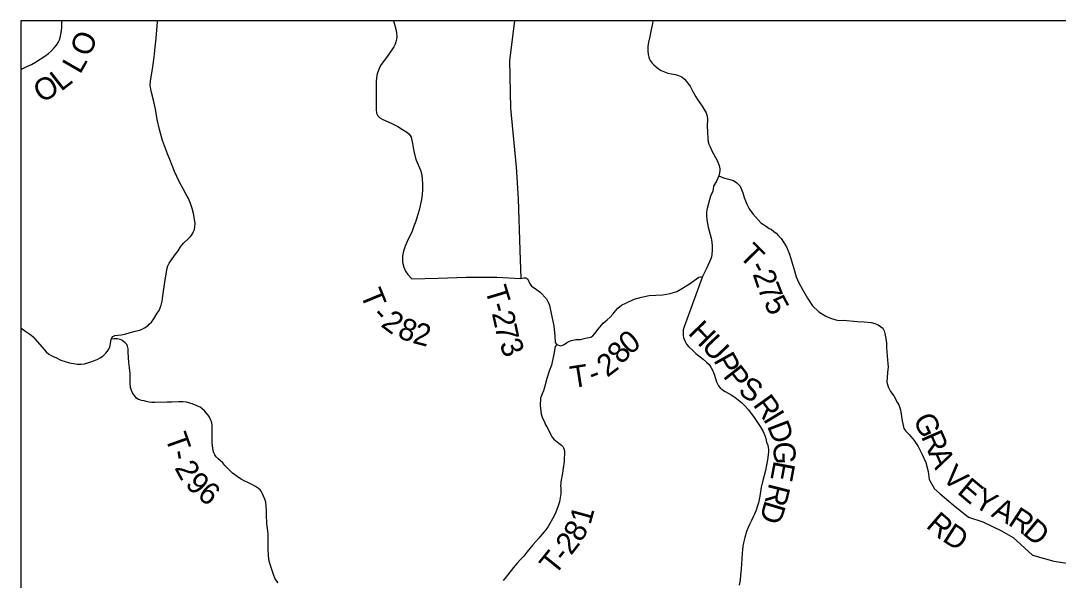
# Model space of a CAD drawing. Extents: x -10.5 to 40.6, y -3.2 to 22.
# Drawn here: x -10.544 to -7.857, y 19.45 to 20.9 of the extents above; entities that cross this region are included whole.
import ezdxf

# ---------------------------------------------------------------- set-up
doc = ezdxf.new("R2010")
doc.units = 0
for name, color, linetype in [('GM_X_County_Road', 7, 'Continuous'), ('GM_X_Township_Road', 7, 'Continuous'), ('GM_X_Township_Road_Text', 7, 'Continuous'), ('GM_X_Township_Text', 7, 'Continuous')]:
    doc.layers.add(name, color=color, linetype=linetype)

msp = doc.modelspace()

# ---------------------------------------------------------------- linework, layer by layer
at = {"layer": 'GM_X_County_Road'}
msp.add_lwpolyline([(-10.5445, 20.104), (-10.5309, 20.0945), (-10.5184, 20.0862), (-10.5127, 20.0809), (-10.5076, 20.0753), (-10.4893, 20.0539), (-10.4786, 20.0422), (-10.4714, 20.036), (-10.4653, 20.0321), (-10.4608, 20.0299), (-10.454, 20.0268), (-10.4403, 20.0206), (-10.4292, 20.0168), (-10.4178, 20.0131), (-10.4077, 20.0112), (-10.398, 20.0103), (-10.3881, 20.0102), (-10.3795, 20.011), (-10.3707, 20.0132), (-10.3606, 20.0168), (-10.3534, 20.019), (-10.3446, 20.0225), (-10.3388, 20.0259), (-10.3321, 20.031), (-10.3243, 20.0385), (-10.3172, 20.0474), (-10.3139, 20.0551), (-10.312, 20.0632), (-10.3099, 20.0751), (-10.3082, 20.0781), (-10.3056, 20.0813), (-10.3009, 20.0839), (-10.2931, 20.0848), (-10.2845, 20.086), (-10.2746, 20.088), (-10.2609, 20.0916), (-10.2482, 20.0952), (-10.2366, 20.0984), (-10.2296, 20.1009), (-10.2235, 20.104), (-10.2157, 20.1094), (-10.2114, 20.1136), (-10.2058, 20.1191), (-10.1995, 20.1278), (-10.1907, 20.1417), (-10.1863, 20.1492), (-10.1835, 20.1556), (-10.1808, 20.1631), (-10.1783, 20.1728), (-10.1761, 20.1867), (-10.171, 20.2227), (-10.1669, 20.2494), (-10.165, 20.2589), (-10.1632, 20.2651), (-10.16, 20.2715), (-10.1542, 20.2803), (-10.1462, 20.2912), (-10.137, 20.3039), (-10.1304, 20.3138), (-10.1263, 20.3194), (-10.1231, 20.3237), (-10.1108, 20.3349), (-10.1044, 20.3409), (-10.1012, 20.345), (-10.0988, 20.3497), (-10.0968, 20.3535), (-10.0948, 20.3587), (-10.0935, 20.366), (-10.0931, 20.3743), (-10.0945, 20.3858), (-10.0973, 20.4005), (-10.1004, 20.413), (-10.1048, 20.4259), (-10.1103, 20.4393), (-10.1156, 20.4499), (-10.1236, 20.4641), (-10.1313, 20.4782), (-10.1402, 20.4967), (-10.1458, 20.5095), (-10.158, 20.54), (-10.164, 20.5554), (-10.1721, 20.5756), (-10.1771, 20.5893), (-10.1848, 20.6177), (-10.191, 20.6443), (-10.1958, 20.6705), (-10.2008, 20.6937), (-10.206, 20.7142), (-10.2078, 20.7226), (-10.2093, 20.733), (-10.2082, 20.7437), (-10.2027, 20.7803), (-10.1989, 20.8054), (-10.1961, 20.8317), (-10.1933, 20.8547), (-10.1907, 20.8868), (-10.1905, 20.8973), (-10.1903, 20.9)], dxfattribs=at)
at = {"layer": 'GM_X_Township_Road'}
for points in [[(-10.5445, 20.7732), (-10.5408, 20.7755), (-10.5289, 20.7813), (-10.5167, 20.787), (-10.5067, 20.7924), (-10.5036, 20.794), (-10.4825, 20.8079), (-10.4723, 20.815), (-10.4647, 20.822), (-10.4579, 20.8295), (-10.452, 20.8365), (-10.4474, 20.8434), (-10.4437, 20.8509), (-10.4411, 20.8604), (-10.4394, 20.8694), (-10.4382, 20.8819), (-10.4381, 20.889), (-10.4384, 20.8953), (-10.4377, 20.9)], [(-9.5792, 20.9), (-9.5772, 20.8933), (-9.5732, 20.8784), (-9.5709, 20.8689), (-9.5703, 20.8584), (-9.5709, 20.8521), (-9.5725, 20.8453), (-9.5746, 20.8396), (-9.5783, 20.8324), (-9.5929, 20.8107), (-9.6122, 20.7836), (-9.6179, 20.772), (-9.6213, 20.762), (-9.623, 20.7529), (-9.6234, 20.7414), (-9.6242, 20.7113), (-9.624, 20.671), (-9.6228, 20.6608), (-9.6193, 20.6539), (-9.6145, 20.6481), (-9.6082, 20.645), (-9.5829, 20.6337), (-9.5681, 20.626), (-9.556, 20.6185), (-9.5447, 20.6114), (-9.5392, 20.6068), (-9.5355, 20.6029), (-9.5335, 20.5986), (-9.5298, 20.5818), (-9.5272, 20.5661), (-9.5255, 20.5583), (-9.5232, 20.5474), (-9.5198, 20.539), (-9.509, 20.5124), (-9.5066, 20.5038), (-9.5055, 20.4978), (-9.5049, 20.4902), (-9.5039, 20.4764), (-9.5038, 20.4631), (-9.5047, 20.4487), (-9.5062, 20.4363), (-9.5123, 20.4088), (-9.5163, 20.3951), (-9.5213, 20.3809), (-9.526, 20.3674), (-9.5307, 20.3547), (-9.5438, 20.3278), (-9.5483, 20.3159), (-9.5532, 20.3027), (-9.556, 20.2898), (-9.5554, 20.2739), (-9.5517, 20.2617), (-9.5475, 20.2511), (-9.5417, 20.2423), (-9.5312, 20.2309), (-9.4636, 20.233), (-9.391, 20.2354), (-9.3113, 20.2354), (-9.2489, 20.2317)], [(-9.2653, 20.9), (-9.2782, 20.7971), (-9.2754, 20.6738), (-9.2614, 20.5209), (-9.2562, 20.4386), (-9.2514, 20.3057), (-9.2489, 20.2317)], [(-8.9073, 20.9), (-8.9084, 20.8932), (-8.9118, 20.8765), (-8.9151, 20.8592), (-8.9179, 20.8446), (-8.9198, 20.8334), (-8.9201, 20.8221), (-8.9191, 20.8128), (-8.9177, 20.806), (-8.9157, 20.8), (-8.914, 20.7967), (-8.9117, 20.7931), (-8.9089, 20.7896), (-8.9048, 20.7857), (-8.8989, 20.7807), (-8.892, 20.7756), (-8.8852, 20.7712), (-8.8771, 20.7673), (-8.8679, 20.7644), (-8.8585, 20.7626), (-8.8488, 20.7605), (-8.8406, 20.7579), (-8.8366, 20.7562), (-8.8313, 20.7534), (-8.8251, 20.7484), (-8.8197, 20.7427), (-8.8146, 20.7356), (-8.8108, 20.7301), (-8.8032, 20.7164), (-8.7957, 20.7029), (-8.7912, 20.6962), (-8.7794, 20.6788), (-8.7738, 20.67), (-8.7693, 20.661), (-8.7667, 20.6527), (-8.7657, 20.6443), (-8.7663, 20.6275), (-8.7653, 20.6108), (-8.7649, 20.5941), (-8.7639, 20.5863), (-8.762, 20.5798), (-8.7589, 20.5729), (-8.754, 20.5628), (-8.7404, 20.5381), (-8.7355, 20.5245), (-8.7337, 20.5162), (-8.7333, 20.512), (-8.7342, 20.5056), (-8.736, 20.498), (-8.742, 20.4838), (-8.7497, 20.4711), (-8.7505, 20.4645), (-8.7519, 20.4587), (-8.7574, 20.4449), (-8.7633, 20.4266), (-8.7669, 20.4096), (-8.7678, 20.403), (-8.7683, 20.3955), (-8.7673, 20.384), (-8.7657, 20.3743), (-8.7635, 20.3646), (-8.7559, 20.3363), (-8.7544, 20.3264), (-8.7534, 20.3165), (-8.753, 20.3054), (-8.754, 20.2942), (-8.7554, 20.2883), (-8.7567, 20.2828), (-8.768, 20.2582), (-8.7788, 20.2372), (-8.8263, 20.1065), (-8.8281, 20.0988), (-8.8288, 20.0915), (-8.8282, 20.0845), (-8.8276, 20.0793), (-8.8261, 20.0747), (-8.8237, 20.069), (-8.8197, 20.0621), (-8.8135, 20.0545), (-8.8047, 20.0458), (-8.7955, 20.0378), (-8.7767, 20.0227), (-8.768, 20.0154), (-8.7615, 20.0086), (-8.7567, 20.0018), (-8.7523, 19.9942), (-8.7484, 19.9839), (-8.745, 19.9723), (-8.7419, 19.9639), (-8.7398, 19.9586), (-8.7372, 19.9541), (-8.7324, 19.9484), (-8.7267, 19.9436), (-8.7196, 19.9389), (-8.7038, 19.9304), (-8.6946, 19.9245), (-8.6858, 19.9178), (-8.6777, 19.9105), (-8.6686, 19.9016), (-8.6597, 19.8913), (-8.6448, 19.8719), (-8.6391, 19.8635), (-8.6292, 19.8487), (-8.6211, 19.835), (-8.6171, 19.825), (-8.6148, 19.8175), (-8.6123, 19.8081), (-8.6096, 19.7997), (-8.6084, 19.7941), (-8.6078, 19.7888), (-8.6076, 19.7815), (-8.6099, 19.7616), (-8.6131, 19.7437), (-8.6154, 19.7344), (-8.6231, 19.7053), (-8.6262, 19.6908), (-8.6302, 19.6679), (-8.6337, 19.6508), (-8.6368, 19.6403), (-8.6394, 19.6315), (-8.6417, 19.6253), (-8.644, 19.6207), (-8.6471, 19.614), (-8.6518, 19.6044), (-8.657, 19.5946), (-8.6604, 19.5868), (-8.6646, 19.5763), (-8.6691, 19.5606), (-8.6726, 19.5471), (-8.674, 19.5384), (-8.6748, 19.529), (-8.6755, 19.5197), (-8.6787, 19.4785), (-8.6799, 19.4627), (-8.6812, 19.45), (-8.6832, 19.4369)], [(-8.736, 20.498), (-8.7244, 20.4931), (-8.6982, 20.4858), (-8.6897, 20.4797), (-8.6811, 20.471), (-8.6739, 20.4536), (-8.6704, 20.4421), (-8.664, 20.4243), (-8.6578, 20.4126), (-8.6484, 20.3994), (-8.6271, 20.3763), (-8.6203, 20.3715), (-8.6151, 20.3686), (-8.6093, 20.3637), (-8.6061, 20.3616), (-8.6006, 20.3595), (-8.5934, 20.3541), (-8.5875, 20.3491), (-8.5812, 20.3427), (-8.5745, 20.3352), (-8.5682, 20.3265), (-8.5608, 20.3142), (-8.5533, 20.2952), (-8.5402, 20.2517), (-8.5358, 20.2365), (-8.5289, 20.2205), (-8.5199, 20.2051), (-8.5068, 20.1812), (-8.4935, 20.1614), (-8.477, 20.1458), (-8.4586, 20.1345), (-8.4468, 20.1291), (-8.433, 20.1245), (-8.4244, 20.1231), (-8.4131, 20.1235), (-8.3781, 20.1205), (-8.3595, 20.1197), (-8.3414, 20.1178), (-8.3323, 20.1157), (-8.3232, 20.1122), (-8.3171, 20.1077), (-8.3115, 20.1032), (-8.3079, 20.0963), (-8.3064, 20.0897), (-8.3037, 20.0765), (-8.3018, 20.0645), (-8.3014, 20.0522), (-8.298, 20.0111), (-8.2972, 20.0033), (-8.2995, 19.9882), (-8.3006, 19.9635), (-8.2977, 19.9507), (-8.2916, 19.939), (-8.2825, 19.9274), (-8.2729, 19.9095), (-8.2701, 19.9043), (-8.2658, 19.8915), (-8.2613, 19.8634), (-8.2565, 19.8432), (-8.2514, 19.8358), (-8.2435, 19.8278), (-8.2304, 19.8118), (-8.2199, 19.7965), (-8.2098, 19.7757), (-8.2, 19.7547), (-8.1939, 19.7314), (-8.1913, 19.7107), (-8.1777, 19.6866), (-8.163, 19.6741), (-8.1287, 19.6457), (-8.0894, 19.6137), (-8.0525, 19.6014), (-8.0038, 19.5779), (-7.9741, 19.561), (-7.9233, 19.5147), (-7.8682, 19.4996), (-7.8285, 19.4929)], [(-9.2489, 20.2317), (-9.2417, 20.2338), (-9.2359, 20.2338), (-9.2311, 20.2306), (-9.2268, 20.2197), (-9.221, 20.2123), (-9.212, 20.2057), (-9.1992, 20.1966), (-9.1823, 20.1792), (-9.1782, 20.1708), (-9.175, 20.1627), (-9.1704, 20.1412), (-9.1638, 20.1096), (-9.1608, 20.0827), (-9.1597, 20.0663), (-9.1554, 20.0609)], [(-9.1554, 20.0609), (-9.1514, 20.0594), (-9.1453, 20.0575), (-9.142, 20.058), (-9.1365, 20.0607), (-9.1307, 20.0649), (-9.1227, 20.0695), (-9.1175, 20.071), (-9.1064, 20.0734), (-9.0943, 20.0741), (-9.0811, 20.077), (-9.0677, 20.08), (-9.0628, 20.0837), (-9.0576, 20.0895), (-9.0483, 20.1005), (-9.0359, 20.1161), (-9.0253, 20.1252), (-9.0178, 20.1315), (-9.0098, 20.14), (-9.0038, 20.1481), (-8.9981, 20.1552), (-8.9886, 20.1628), (-8.9753, 20.1691), (-8.9551, 20.1782), (-8.9365, 20.1832), (-8.9164, 20.1882), (-8.8997, 20.1883), (-8.881, 20.1897), (-8.8624, 20.1932), (-8.8448, 20.1981), (-8.8299, 20.2068), (-8.8124, 20.2184), (-8.7876, 20.2352), (-8.784, 20.2365), (-8.7788, 20.2372)], [(-10.2221, 19.9143), (-10.225, 19.9151), (-10.2313, 19.9161), (-10.2358, 19.917), (-10.2396, 19.9185), (-10.2436, 19.921), (-10.2474, 19.9248), (-10.251, 19.9293), (-10.2546, 19.9355), (-10.2578, 19.9417), (-10.2598, 19.9494), (-10.2612, 19.9603), (-10.2612, 19.9769), (-10.261, 19.9859), (-10.2629, 20.0005), (-10.2642, 20.0145), (-10.2661, 20.0408), (-10.2666, 20.0493), (-10.2682, 20.0564), (-10.27, 20.061), (-10.274, 20.0653), (-10.278, 20.0686), (-10.2827, 20.0718), (-10.2868, 20.0738), (-10.2948, 20.0757), (-10.3022, 20.0759), (-10.3099, 20.0751)], [(-9.1554, 20.0609), (-9.16, 20.0557), (-9.1634, 20.0354), (-9.17, 20.007), (-9.1757, 19.9913), (-9.1817, 19.9727), (-9.1866, 19.9525), (-9.1884, 19.9467), (-9.1903, 19.9408), (-9.1939, 19.9326), (-9.1984, 19.922), (-9.199, 19.903), (-9.1974, 19.8878), (-9.1965, 19.8799), (-9.1949, 19.8751), (-9.1935, 19.8723), (-9.1865, 19.8581), (-9.1852, 19.853), (-9.1814, 19.848), (-9.1711, 19.8268), (-9.1684, 19.8215), (-9.1634, 19.8151), (-9.151, 19.8054), (-9.1434, 19.7997), (-9.1403, 19.7965), (-9.1386, 19.7934), (-9.1369, 19.7887), (-9.1359, 19.7825), (-9.1356, 19.7767), (-9.1364, 19.7662), (-9.1372, 19.7572), (-9.1391, 19.7402), (-9.1411, 19.7277), (-9.1452, 19.7052), (-9.1458, 19.7005), (-9.1459, 19.6957), (-9.1452, 19.6879), (-9.1452, 19.6781), (-9.1455, 19.674), (-9.1461, 19.6689), (-9.1491, 19.6531), (-9.1529, 19.64), (-9.1586, 19.6259), (-9.1638, 19.6154), (-9.1784, 19.5893), (-9.1846, 19.5802), (-9.19, 19.5739), (-9.2028, 19.5586), (-9.2176, 19.5418), (-9.2331, 19.5222), (-9.2416, 19.5124), (-9.2497, 19.504), (-9.2585, 19.4937), (-9.2642, 19.4872), (-9.2874, 19.4587), (-9.2947, 19.4494)], [(-9.8774, 19.4428), (-9.8834, 19.4505), (-9.8864, 19.4556), (-9.8892, 19.4623), (-9.8968, 19.4856), (-9.9007, 19.4991), (-9.9026, 19.5141), (-9.9039, 19.5309), (-9.9037, 19.553), (-9.9037, 19.5696), (-9.9045, 19.5778), (-9.9073, 19.596), (-9.9075, 19.6206), (-9.908, 19.6318), (-9.9085, 19.6411), (-9.9099, 19.6524), (-9.9122, 19.66), (-9.9154, 19.6679), (-9.9187, 19.6754), (-9.9213, 19.6805), (-9.9243, 19.6841), (-9.9288, 19.6879), (-9.9363, 19.6925), (-9.9438, 19.6971), (-9.9565, 19.7032), (-9.9657, 19.7077), (-9.9733, 19.7121), (-9.98, 19.7162), (-9.9877, 19.7216), (-9.9956, 19.7276), (-10.0043, 19.7359), (-10.0158, 19.7469), (-10.0214, 19.7541), (-10.0282, 19.7599), (-10.0332, 19.7647), (-10.0379, 19.7698), (-10.0415, 19.7751), (-10.0442, 19.7801), (-10.0464, 19.7864), (-10.0478, 19.7986), (-10.0484, 19.8062), (-10.0485, 19.8208), (-10.0489, 19.8527), (-10.0504, 19.8614), (-10.0535, 19.8683), (-10.0568, 19.8743), (-10.0602, 19.8787), (-10.0635, 19.8829), (-10.0684, 19.8889), (-10.075, 19.8948), (-10.0799, 19.8983), (-10.0843, 19.9005), (-10.0901, 19.903), (-10.1001, 19.907), (-10.1068, 19.9092), (-10.1115, 19.9105), (-10.1158, 19.9111), (-10.1243, 19.9119), (-10.1348, 19.9119), (-10.1532, 19.9116), (-10.1655, 19.9115), (-10.1969, 19.9103), (-10.2048, 19.9105), (-10.2119, 19.9112), (-10.2159, 19.9122), (-10.2192, 19.9135), (-10.2221, 19.9143)]]:
    msp.add_lwpolyline(points, dxfattribs=at)
at = {"layer": 'GM_X_Township_Text'}
msp.add_lwpolyline([(-6.192, 17.3965), (-6.1792, 18.1778), (-6.179, 18.1863), (-6.1678, 18.8746), (-6.1678, 18.8755), (-6.1618, 20.9), (-10.5445, 20.9), (-10.5445, 19.4241)], dxfattribs=at)

# ---------------------------------------------------------------- texts
at = {"layer": 'GM_X_Township_Road_Text'}
for s, rotation, p in [('O', 68.0961, (-10.3661, 20.8041)), ('L', 60.1092, (-10.391, 20.7595)), ('O', 29.7471, (-10.491, 20.6856)), ('L', 37.9571, (-10.4402, 20.7153)), ('T', 314.9485, (-8.6864, 20.2888)), ('-', 297.6055, (-8.659, 20.2624)), ('2', 288.6785, (-8.6491, 20.2439)), ('T', 292.3601, (-9.666, 20.192)), ('T', 286.7772, (-9.3426, 20.204)), ('7', 291.5766, (-8.6368, 20.2078)), ('5', 297.7572, (-8.6212, 20.1692)), ('-', 285.4071, (-9.3305, 20.1637)), ('-', 312.8616, (-9.638, 20.1341)), ('2', 322.9202, (-9.6141, 20.1097)), ('2', 282.644, (-9.3244, 20.1419)), ('8', 338.6116, (-9.5714, 20.0804)), ('2', 345.4553, (-9.5317, 20.0653)), ('7', 281.9937, (-9.3168, 20.1079)), ('H', 314.2375, (-8.8181, 20.0892)), ('3', 293.18, (-9.3059, 20.0621)), ('0', 38.4136, (-8.967, 20.0324)), ('U', 313.4389, (-8.7834, 20.0535)), ('8', 52.6308, (-8.9856, 20.0072)), ('2', 37.2426, (-9.0252, 19.9743)), ('P', 299.1414, (-8.7512, 20.0202)), ('T', 9.0459, (-9.1167, 19.9474)), ('P', 308.1364, (-8.7271, 19.9786)), ('-', 21.0139, (-9.0623, 19.9574)), ('S', 326.3499, (-8.689, 19.9351)), ('R', 305.6411, (-8.6493, 19.9046)), ('I', 301.2864, (-8.6228, 19.8676)), ('D', 290.947, (-8.6118, 19.8501)), ('G', 294.4777, (-8.2338, 19.8678)), ('T', 289.469, (-10.1713, 19.8208)), ('R', 293.7659, (-8.2131, 19.8225)), ('-', 279.8371, (-10.1578, 19.7832)), ('G', 271.5447, (-8.5949, 19.8084)), ('A', 293.212, (-8.1944, 19.7799)), ('2', 298.4795, (-10.1472, 19.7413)), ('E', 259.4188, (-8.5934, 19.7616)), ('V', 316.4995, (-8.1604, 19.7134)), ('9', 313.9436, (-10.1207, 19.697)), ('6', 321.8, (-10.0901, 19.6661)), ('E', 319.9548, (-8.1213, 19.6765)), ('R', 256.1105, (-8.6051, 19.7036)), ('Y', 330.452, (-8.0795, 19.6427)), ('D', 253.5157, (-8.6161, 19.659)), ('A', 333.7813, (-8.0328, 19.6163)), ('1', 74.7389, (-9.0688, 19.5917)), ('R', 319.2484, (-8.2019, 19.5885)), ('R', 326.9768, (-7.9895, 19.5951)), ('8', 58.84, (-9.0937, 19.546)), ('D', 327.1787, (-8.1598, 19.553)), ('D', 320.2131, (-7.9518, 19.5707)), ('2', 52.3664, (-9.119, 19.5125)), ('T', 51.124, (-9.1611, 19.4601)), ('-', 51.3386, (-9.1343, 19.4934))]:
    msp.add_text(s, height=0.0568, rotation=rotation, dxfattribs=at).set_placement(p)

doc.saveas('drawing.dxf')
